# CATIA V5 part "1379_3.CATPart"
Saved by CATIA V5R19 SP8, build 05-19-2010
Part number: 3
Bounding box of the stored display mesh (mm): x -3.931 to 3.931, y -3.967 to 3.967, z 28.411 to 106.908
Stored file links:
  C:\Users\ThinkMotion\Desktop\EU_thinkMotion\iao\IAO_MMS_Groupe3\bblot\bblot\1379_3.CATPart
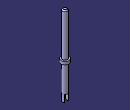
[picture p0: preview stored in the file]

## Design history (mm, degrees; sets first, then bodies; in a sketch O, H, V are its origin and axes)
Body1 (main body)
  Line1: stored without definition
  Sketch1 on yz-plane, origin (0, 0, 0), H (0, 1, 0), V (0, 0, 1)
    line L1 (0, 27.9082) -> (2.5, 27.9082)
    line L2 (2.5, 27.9082) -> (2.5, 61.9082)
    line L3 (2.5, 61.9082) -> (4, 61.9082)
    line L4 (4, 61.9082) -> (4, 64.9082)
    line L5 (4, 64.9082) -> (2.5, 64.9082)
    point P5 (2.5, 64.9082)
    line L6 (2.5, 64.9082) -> (2.5, 106.9082)
    line L7 (2.5, 106.9082) -> (0, 106.9082)
    line L8 (0, 27.9082) -> (0, 106.9082)
    axis line L9 (0, 27.9082) -> (0, 72.3948)
    reference projected line E1 through (0, 0) direction (0, 1) from Line1
    length L8 = 79
    length L2 = 34
    length L4 = 3
    distance L8 L6 = 2.5
    distance L4 L8 = 4
    horizontal: L1 H, L3 H, L5 H, L7 H
    vertical: L2 V, L4 V, L6 V, L8 V, L9 V
    coincidence: P5 L2, L8 E1
  Shaft1: profile Sketch1, axis Sketch1.L9, angle 360
  Chamfer1: length 1, angle 45, on edge [face of Shaft1 from Sketch1.L6 | face of Shaft1 from Sketch1.L7]; edge [face of Shaft1 from Sketch1.L1 | face of Shaft1 from Sketch1.L2]
  Sketch2 on face of Shaft1 from Sketch1.L1, origin (0, 0, 27.9082), H (1, 0, 0), V (0, -1, 0)
    line L1 (-2, 2.5) -> (2, 2.5)
    line L2 (2, 2.5) -> (2, -2.5)
    line L3 (2, -2.5) -> (-2, -2.5)
    line L4 (-2, -2.5) -> (-2, 2.5)
    axis line L5 (0, 2.5) -> (0, -2.5)
    point P5 (0, 2.5)
    point P6 (0, -2.5)
    reference projected circle E1 centre (0, 0) radius 2.5 from edge [face of Chamfer1 | face of Shaft1 from Sketch1.L2]
    reference projected circle E2 centre (0, 0) radius 2.5 from edge [face of Chamfer1 | face of Shaft1 from Sketch1.L2]
    reference intersected line E3 through (0, 0) direction (0, 1) from yz-plane
    length L1 = 4
    horizontal: L1 H, L3 H
    vertical: L2 V, L4 V, L5 V
    coincidence: P5 L1, P6 L3, E3 L5
    midpoint: P5 L1
    tangency: L1 E1, L3 E2
  Pocket1: profile Sketch2, direction (0, 0, 1), length 8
